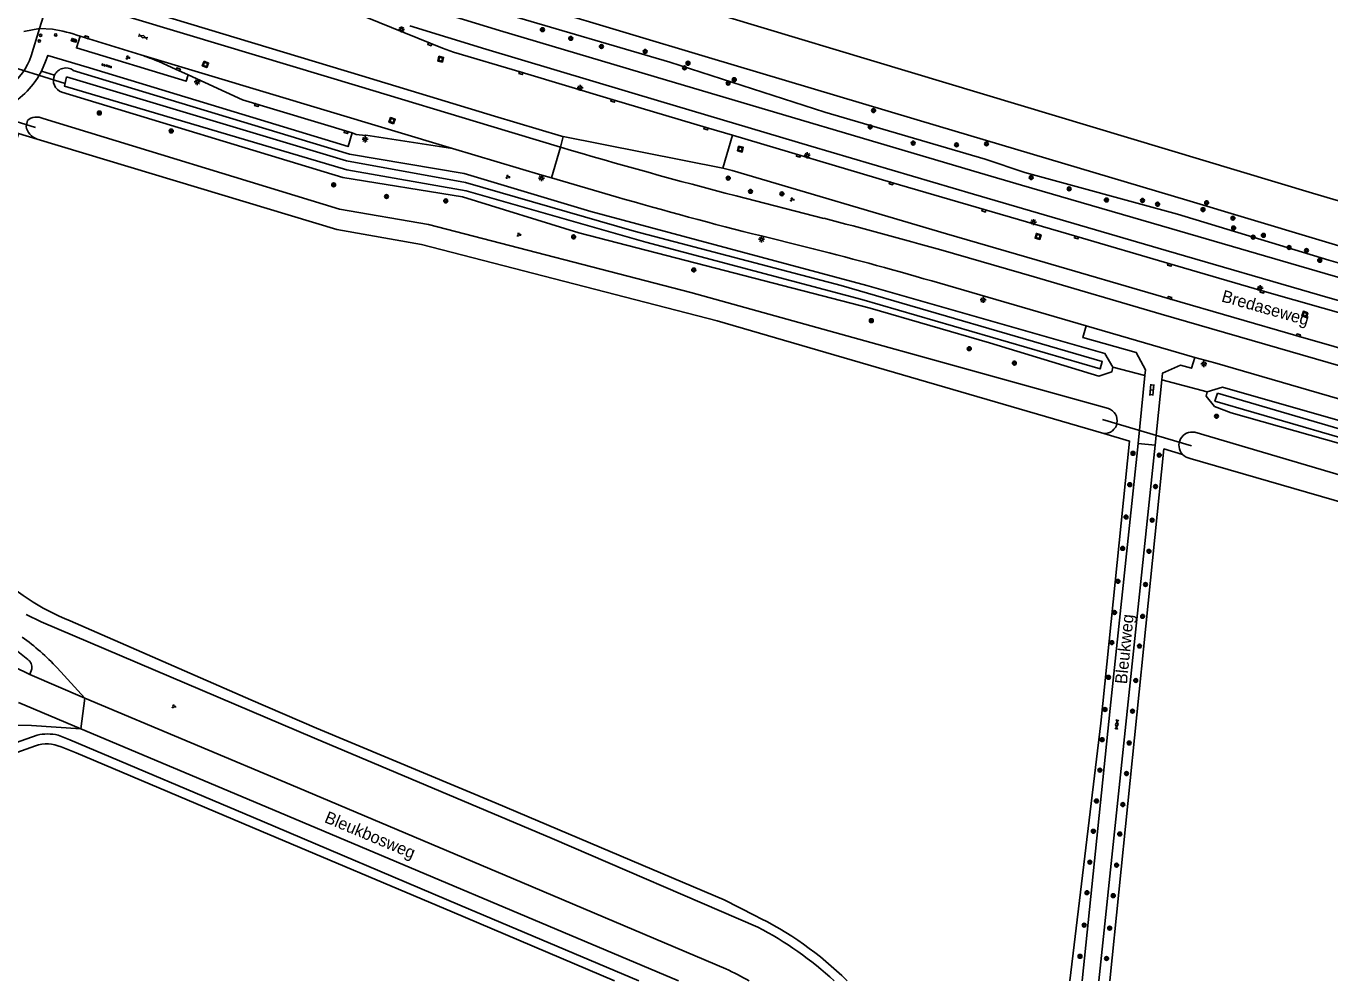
# Model space of a CAD drawing. Extents: x 125000 to 129004, y 397500 to 399008.
# Drawn here: x 126547.3 to 126817.1, y 397500 to 397697.5 of the extents above; entities that cross this region are included whole.
import ezdxf

# ---------------------------------------------------------------- set-up
doc = ezdxf.new("R2010")
doc.units = 0
for name, color, linetype in [('gg-afsc-draadraster', 7, 'Continuous'), ('gg-afsc-hekwerk', 7, 'Continuous'), ('gg-afsc-lijn draadraster', 7, 'Continuous'), ('gg-anno-openbare ruimte label', 7, 'Continuous'), ('gg-knt-bronhoudergrens', 7, 'Continuous'), ('gg-knt-verharding', 7, 'Continuous'), ('gg-knt-verharding nz', 7, 'Continuous'), ('gg-kntw-greppel-droge sloot', 7, 'Continuous'), ('gg-kntw-waterlijn', 7, 'Continuous'), ('gg-kwrk-duiker nz buis', 7, 'Continuous'), ('gt-grn-groengrens', 7, 'Continuous'), ('gt-grn-weggrens', 7, 'Continuous'), ('gt-symb-boom', 7, 'Continuous'), ('gt-symb-drukknoppaal', 7, 'Continuous'), ('gt-symb-gesloten verharding', 7, 'Continuous'), ('gt-symb-groenvak', 7, 'Continuous'), ('gt-symb-klinker verharding', 7, 'Continuous'), ('gt-symb-kolk', 7, 'Continuous'), ('gt-symb-lichtmast', 7, 'Continuous'), ('gt-symb-rioolschacht', 7, 'Continuous'), ('gt-symb-tegel verharding', 7, 'Continuous'), ('gt-symb-verkeersregelinstallatiekast', 7, 'Continuous'), ('gt-symb-verkeersregelinstallatiepaal', 7, 'Continuous'), ('gx-grn-maaiveld', 7, 'Continuous')]:
    doc.layers.add(name, color=color, linetype=linetype)

# ---------------------------------------------------------------- blocks, each defined once
blk = doc.blocks.new('gt0-BOOM')
at = {"layer": 'gt-symb-boom'}
for radius in [0.4, 0.2]:
    blk.add_circle((0, 0), radius, dxfattribs=at)
blk = doc.blocks.new('gt0-KOLK')
at = {"layer": 'gt-symb-kolk'}
blk.add_lwpolyline([(0, 0), (0.37, 0), (0.37, 0.4), (-0.38, 0.4), (-0.38, 0), (0, 0)], dxfattribs=at)
blk = doc.blocks.new('gt0-RS')
at = {"layer": 'gt-symb-rioolschacht'}
blk.add_lwpolyline([(-0.5, -0.5), (0.5, -0.5), (0.5, 0.5), (-0.5, 0.5)], close=True, dxfattribs=at)
blk.add_circle((0, 0), 0.375, dxfattribs=at)
blk = doc.blocks.new('gt0-LMAST')
at = {"layer": 'gt-symb-lichtmast'}
for p, q in [((-0.18, 0.17), (-0.45, 0.44)), ((-0.01, 0.25), (-0.01, 0.62)), ((0.17, 0.17), (0.44, 0.44)), ((-0.26, 0), (-0.63, 0)), ((-0.18, -0.18), (-0.45, -0.45)), ((-0.01, -0.25), (-0.01, -0.63)), ((0.44, -0.45), (0.17, -0.18)), ((0.24, 0), (0.62, 0))]:
    blk.add_line(p, q, dxfattribs=at)
blk.add_circle((-0.01, 0), 0.25, dxfattribs=at)
blk = doc.blocks.new('gt0-KL1')
at = {"layer": 'gt-symb-klinker verharding'}
for p, q in [((-1.15, 0.3), (1.15, 0.3)), ((-1, -0.3), (-1, 0.3)), ((-0.5, 0.3), (-0.5, 0.45)), ((0, -0.3), (0, 0.3)), ((0.5, 0.3), (0.5, 0.45)), ((1, -0.3), (1, 0.3)), ((-1.15, -0.3), (1.15, -0.3)), ((-0.5, -0.45), (-0.5, -0.3)), ((0.5, -0.45), (0.5, -0.3))]:
    blk.add_line(p, q, dxfattribs=at)
blk = doc.blocks.new('gt0-GESVH1')
at = {"layer": 'gt-symb-gesloten verharding'}
for p, q in [((-0.99, -0.26), (0.01, 0.24)), ((0.01, -0.26), (-0.99, 0.24)), ((0.01, 0.24), (1.01, -0.26)), ((1.01, 0.24), (0.01, -0.26))]:
    blk.add_line(p, q, dxfattribs=at)
blk = doc.blocks.new('gt0-GRVAK')
at = {"layer": 'gt-symb-groenvak'}
for p, q in [((-0.11, 0.19), (-0.23, 0.24)), ((-0.18, 0.15), (0.09, 0.15)), ((-0.09, 0.21), (-0.16, 0.32)), ((-0.05, 0.21), (-0.05, 0.39)), ((0, 0.21), (0.06, 0.32)), ((0.01, 0.19), (0.13, 0.24)), ((0.26, -0.05), (0.2, 0.06)), ((0.3, -0.05), (0.3, 0.13)), ((0.35, -0.05), (0.41, 0.06)), ((-0.24, -0.23), (-0.36, -0.18)), ((-0.32, -0.26), (-0.05, -0.26)), ((-0.23, -0.21), (-0.29, -0.09)), ((-0.18, -0.2), (-0.18, -0.02)), ((-0.14, -0.21), (-0.07, -0.09)), ((-0.12, -0.23), (0, -0.18)), ((0.24, -0.07), (0.12, -0.02)), ((0.17, -0.11), (0.44, -0.11)), ((0.37, -0.07), (0.49, -0.02))]:
    blk.add_line(p, q, dxfattribs=at)
blk = doc.blocks.new('gt0-TEG1')
at = {"layer": 'gt-symb-tegel verharding'}
for p, q in [((-1.12, 0), (1.12, 0)), ((-0.9, -0.25), (-0.9, 0.25)), ((-0.45, -0.25), (-0.45, 0.25)), ((0, -0.25), (0, 0.25)), ((0.45, -0.25), (0.45, 0.25)), ((0.9, -0.25), (0.9, 0.25))]:
    blk.add_line(p, q, dxfattribs=at)
blk = doc.blocks.new('gt0-DPAAL')
at = {"layer": 'gt-symb-drukknoppaal'}
blk.add_circle((0, 0), 0.25, dxfattribs=at)
blk = doc.blocks.new('gt0-VIPAAL')
at = {"layer": 'gt-symb-verkeersregelinstallatiepaal'}
blk.add_circle((0, 0), 0.25, dxfattribs=at)
blk = doc.blocks.new('gt0-VRIKST')
at = {"layer": 'gt-symb-verkeersregelinstallatiekast'}
for p, q in [((-0.5, -0.25), (0.5, 0.25)), ((-0.5, 0.25), (0.5, -0.25))]:
    blk.add_line(p, q, dxfattribs=at)
blk.add_lwpolyline([(0.5, 0.25), (-0.5, 0.25), (-0.5, -0.25), (0.5, -0.25)], close=True, dxfattribs=at)

msp = doc.modelspace()

# ---------------------------------------------------------------- linework, layer by layer
at = {"layer": 'gg-afsc-draadraster'}
msp.add_lwpolyline([(126680.86, 397850.53), (126672.24, 397845.08), (126589.63, 397738.35), (126608.57, 397724.72), (126813.52, 397663.01), (126844.57, 397653.81), (126855.71, 397650.92), (126946.81, 397622.37)], dxfattribs=at)
at = {"layer": 'gg-afsc-hekwerk'}
msp.add_lwpolyline([(126942.42, 397614.98), (126787.49, 397661.55), (126736.33, 397676.77), (126688.51, 397691.05), (126603.35, 397716.66)], dxfattribs=at)
msp.add_lwpolyline([(126942.42, 397614.98), (126787.49, 397661.55), (126736.33, 397676.77), (126688.51, 397691.05), (126603.35, 397716.66)], dxfattribs=at)
at = {"layer": 'gg-afsc-lijn draadraster'}
msp.add_lwpolyline([(126680.86, 397850.53), (126672.24, 397845.08), (126589.63, 397738.35), (126608.57, 397724.72), (126813.52, 397663.01), (126844.57, 397653.81), (126855.71, 397650.92), (126946.81, 397622.37)], dxfattribs=at)
at = {"layer": 'gg-knt-bronhoudergrens'}
for points in [[(126770.33, 397613.24), (126775.63, 397611.69), (126769.68, 397553.36), (126763.27, 397500)], [(126771.58, 397500), (126782.74, 397610.06), (126786.6, 397608.92)]]:
    msp.add_lwpolyline(points, dxfattribs=at)
at = {"layer": 'gg-knt-verharding'}
for p, q in [((126550.12, 397697.05), (126548.39, 397691.37)), ((126552.77, 397696.88), (126550.12, 397697.05)), ((126558.48, 397695.44), (126571.04, 397691.59)), ((126548.76, 397685.53), (126549.34, 397686.32)), ((126657.88, 397672.5), (126658.45, 397674.67)), ((126691.46, 397668.17), (126658.45, 397674.67)), ((126656.03, 397666.13), (126669.42, 397662.24)), ((126694.23, 397662.4), (126712.39, 397657.77)), ((126699.49, 397654.13), (126708.53, 397651.9)), ((126734.74, 397644.82), (126766.63, 397635.54)), ((126789.12, 397629.01), (126766.63, 397635.54)), ((126778.8, 397625.25), (126777.44, 397611.22)), ((126780.96, 397610.84), (126782.32, 397624.33)), ((126769.26, 397500), (126780.96, 397610.84)), ((126777.44, 397611.22), (126780.96, 397610.84)), ((126544.88, 397564.97), (126548.12, 397563.37)), ((126548.12, 397563.37), (126548.48, 397564.54)), ((126559.45, 397558.5), (126553.73, 397564.75)), ((126558.64, 397552.15), (126596.99, 397536.04)), ((126596.99, 397536.04), (126682.31, 397500))]:
    msp.add_line(p, q, dxfattribs=at)
for points in [[(126693.46, 397674.95), (126688.05, 397676.56), (126668.8, 397682.27), (126649.75, 397688.02), (126635.77, 397692.15), (126633.47, 397693), (126630.93, 397693.98), (126612.38, 397701.55), (126602.9, 397705.38), (126600.29, 397706.25), (126593.1, 397708.42), (126576.92, 397713.35), (126561.25, 397718.17), (126560.98, 397718.24)], [(126556, 397705.65), (126581.4, 397697.91), (126616.79, 397687.26), (126644.23, 397678.88), (126658.09, 397674.74), (126658.45, 397674.67)], [(126555.31, 397703.49), (126580.59, 397695.82), (126616.12, 397685.12), (126643.45, 397676.83), (126657.88, 397672.5)], [(126898.05, 397622.91), (126846.72, 397637.56), (126816.13, 397646.34), (126784.36, 397655.62), (126753.25, 397664.65), (126744.62, 397667.19), (126679.83, 397686.37), (126645.26, 397696.66), (126630.36, 397701.2)], [(126958.64, 397601.65), (126955.76, 397602.08), (126952.55, 397602.68), (126946.55, 397604.46), (126929.88, 397609.18), (126896.65, 397618.5), (126870.61, 397625.99), (126845.69, 397633.05), (126815.03, 397641.9), (126783.19, 397651.1), (126743.33, 397662.77), (126709.67, 397672.73), (126678.64, 397681.95), (126642.42, 397692.79), (126626.7, 397697.63)], [(126558.48, 397695.44), (126557.73, 397693.02), (126580.46, 397686.14), (126580.88, 397687.43)], [(126614.78, 397675.43), (126613.93, 397672.63), (126560.41, 397688.91), (126551.82, 397691.49), (126551.36, 397690.19)], [(126574.8, 397690.21), (126578.26, 397688.65), (126580.88, 397687.43)], [(126580.88, 397687.43), (126592.07, 397682.3), (126614.78, 397675.43)], [(126614.78, 397675.43), (126615.62, 397675.15), (126617.56, 397674.89), (126617.6, 397674.99), (126635.57, 397672.25)], [(127217.52, 397528.12), (127216.66, 397528.36), (127174.98, 397539.4), (127133.48, 397550.52), (127112.67, 397556.13), (127072.64, 397567.02), (127034.07, 397577.58), (126995.54, 397588.26), (126956.98, 397599.02), (126937.75, 397604.4), (126917.42, 397610.12), (126899.33, 397615.25), (126880, 397620.69), (126860.79, 397626.22), (126841.44, 397631.74), (126822.25, 397637.29), (126803.1, 397642.8), (126783.96, 397648.35), (126764.71, 397653.99), (126745.56, 397659.57), (126726.38, 397665.2), (126693.46, 397674.95)], [(126635.57, 397672.25), (126654, 397666.72), (126656.03, 397666.13)], [(127229.02, 397517.84), (127201.79, 397525.03), (127175.21, 397532.08), (127124.03, 397545.78), (127099.13, 397552.5), (127072.79, 397559.71), (127046.84, 397566.77), (126995.54, 397580.92), (126968.7, 397588.42), (126944.12, 397595.31), (126902.34, 397607.09), (126846.79, 397622.95), (126810.53, 397633.38), (126783.9, 397641.11), (126756.49, 397649.1), (126737.73, 397654.58), (126693.39, 397667.65), (126691.46, 397668.17)], [(127228.13, 397514.43), (127201.09, 397521.57), (127174.12, 397528.76), (127147.75, 397535.83), (127123.09, 397542.48), (127098.21, 397549.13), (127071.78, 397556.36), (127045.92, 397563.39), (126994.69, 397577.57), (126943.18, 397591.97), (126900.68, 397603.95), (126873.36, 397611.7), (126840.83, 397621.01), (126782.2, 397637.97), (126755.87, 397645.68), (126736.59, 397651.23)], [(126766.63, 397635.54), (126765.97, 397633.09), (126777.01, 397630.01), (126778.92, 397626.46), (126778.8, 397625.25)], [(126782.32, 397624.33), (126782.47, 397625.76), (126786.15, 397627.41), (126788.46, 397626.76), (126789.12, 397629.01)], [(127226.37, 397507.68), (127213.45, 397511.07), (127212.8, 397511.23), (127212.87, 397511.61), (127203.25, 397514.16), (127179.75, 397520.34), (127157.76, 397526.2), (127111.36, 397538.68), (127090.71, 397544.26), (127065.54, 397551.12), (127043.84, 397557.07), (127020.85, 397563.46), (126998.29, 397569.62), (126967.67, 397578.26), (126942.81, 397585.13), (126939.99, 397585.87), (126928.21, 397589.18), (126906.39, 397595.25), (126882.62, 397602.07), (126860.21, 397608.45), (126793.27, 397627.87), (126789.12, 397629.01)], [(126765.85, 397500), (126771.65, 397556.38), (126777.44, 397611.22)], [(126547.69, 397566.5), (126545.27, 397568.41), (126540.55, 397571.7)], [(126692.11, 397502.47), (126649.94, 397520.39), (126603.49, 397540.04), (126559.45, 397558.5)], [(126544.19, 397552.88), (126548.47, 397552.84), (126558.64, 397552.15)]]:
    msp.add_lwpolyline(points, dxfattribs=at)
for centre, radius, start, end in [((126549.02, 397670), 27.14, 69.5919, 82.0525), ((126534.84, 397696.3), 14.42, 308.6514, 340.0221), ((126557.21, 397648.26), 45.48, 67.2447, 72.2957), ((126534.6, 397696.43), 17.88, 305.9376, 322.4178), ((126968.34, 398720.06), 1092.6, 253.49189, 255.47078), ((126885.01, 398401.51), 770.07, 253.74218, 256.05935), ((126484.84, 396767.97), 918.44, 74.09133, 75.65505), ((126530.89, 396942.35), 731.44, 73.81825, 75.94442), ((126520.92, 397534.82), 44.41, 42.3806, 54.8381), ((126546.64, 397564.94), 1.88, 347.598, 56.2456), ((126669.46, 397452.63), 54.75, 59.9139, 65.5588)]:
    msp.add_arc(centre, radius, start, end, dxfattribs=at)
at = {"layer": 'gg-knt-verharding nz'}
for p, q in [((126552.36, 397704.36), (126550.12, 397697.05)), ((126550.12, 397697.05), (126546.84, 397696.42)), ((126571.04, 397691.59), (126635.57, 397672.25)), ((126657.88, 397672.5), (126656.03, 397666.13)), ((126691.46, 397668.17), (126693.46, 397674.95)), ((126548.12, 397563.37), (126559.45, 397558.5)), ((126558.64, 397552.15), (126545.74, 397557.58))]:
    msp.add_line(p, q, dxfattribs=at)
at = {"layer": 'gg-kntw-greppel-droge sloot'}
for p, q in [((126547.32, 397676.8), (126547.58, 397678.01)), ((126547.32, 397676.8), (126547.58, 397678.01)), ((126789.14, 397613.5), (126867.11, 397590.56)), ((126864.12, 397586.03), (126788.2, 397608.08)), ((126717.14, 397500.07), (126717.2, 397500))]:
    msp.add_line(p, q, dxfattribs=at)
for points in [[(126938.38, 397612.66), (126919.74, 397618.29), (126894.23, 397626.51), (126874.77, 397632.03), (126847.78, 397640.26), (126816.86, 397649.13), (126785.57, 397658.6), (126753.96, 397667.27), (126745.79, 397670), (126712.61, 397679.71), (126680.54, 397690.07), (126646.67, 397699.99), (126630.26, 397705.04), (126604.63, 397714.07), (126588.73, 397725.07), (126576.4, 397735.35), (126577.59, 397737.11)], [(126772.21, 397626.98), (126770.54, 397629.81), (126721.3, 397643.88), (126664.14, 397659.17), (126637.93, 397667.05), (126614.27, 397671.08), (126557.05, 397688.39)], [(126554.7, 397683.88), (126612.88, 397666.2), (126637.59, 397662.2), (126661.71, 397654.8), (126721.96, 397639.21), (126746.67, 397632), (126769.25, 397625.09), (126771.94, 397626.01), (126772.21, 397626.98)], [(126771.29, 397618.41), (126684.88, 397642.42), (126630.57, 397656.48), (126612.19, 397659.7), (126550.84, 397678.42)], [(126771.29, 397618.41), (126684.88, 397642.42), (126630.57, 397656.48), (126612.19, 397659.7), (126550.84, 397678.42)], [(126770.33, 397613.24), (126690.28, 397636.59), (126629.11, 397652.39), (126611.62, 397655.49), (126549.6, 397674.17)], [(126770.33, 397613.24), (126690.28, 397636.59), (126629.11, 397652.39), (126611.62, 397655.49), (126549.6, 397674.17)], [(126796.66, 397617.51), (126793.22, 397618.81), (126791.48, 397621), (126791.71, 397621.87)], [(126791.71, 397621.87), (126794.89, 397622.82), (126870.78, 397601.15), (126914.48, 397588.79), (126958.33, 397576.51), (126959.95, 397575.77), (126961.59, 397573.52)], [(126961.59, 397573.52), (126961.42, 397572.83), (126958.13, 397571.91), (126919.94, 397582.63), (126868.86, 397597.15), (126796.66, 397617.51)], [(126698.7, 397511.14), (126656.17, 397529.46), (126607.01, 397550.23), (126550.43, 397574.26), (126547.32, 397575.83)], [(126698.11, 397513.52), (126691.75, 397516.8), (126644.56, 397536.77), (126607.39, 397552.32), (126593.82, 397558.12), (126556.41, 397574.49)], [(126507.55, 397500), (126526.89, 397536.86), (126537.5, 397546.58), (126549.6, 397550.87)], [(126509.43, 397500), (126528.29, 397535.76), (126538.37, 397544.78), (126549.25, 397548.62)], [(126553.94, 397550.86), (126556.35, 397549.89), (126596.2, 397533.06), (126637.09, 397515.64), (126674.1, 397500)], [(126554.56, 397548.42), (126557.69, 397547.21), (126595.95, 397530.95), (126635.47, 397514.31), (126669.04, 397500)]]:
    msp.add_lwpolyline(points, dxfattribs=at)
for centre, radius, start, end in [((126555.55, 397686.31), 2.57, 54.2291, 154.6382), ((126549.55, 397675.57), 3.14, 65.5367, 128.8126), ((126549.55, 397675.57), 3.14, 65.5367, 128.8126), ((126550.75, 397677.48), 3.5, 191.1604, 250.7995), ((126550.75, 397677.48), 3.5, 191.1604, 250.7995), ((126770.42, 397615.89), 2.66, 267.9446, 71.0264), ((126770.42, 397615.89), 2.66, 267.9446, 71.0264), ((126788.61, 397610.8), 2.75, 78.9293, 222.9551), ((126788.62, 397610.8), 2.75, 222.9647, 261.3264), ((126573.25, 397617.23), 45.93, 199.8408, 248.4933), ((126551.76, 397540.65), 10.44, 77.9511, 101.9433), ((126551.65, 397541.94), 7.09, 65.805, 109.7475), ((126667.66, 397450.26), 70.21, 45.1917, 64.301), ((126663.67, 397444.51), 75.28, 47.4926, 62.2668)]:
    msp.add_arc(centre, radius, start, end, dxfattribs=at)
at = {"layer": 'gg-kntw-waterlijn'}
for points in [[(126555.68, 397687.05), (126613.62, 397669.68), (126638.25, 397665.22), (126673.15, 397655.1), (126715.98, 397643.87), (126769.98, 397628.14), (126769.54, 397626.62), (126720.25, 397640.98), (126675.55, 397652.87), (126638.35, 397663.45), (126613.67, 397667.79), (126555.25, 397685.12), (126555.68, 397687.05)], [(126793.84, 397621.57), (126824.69, 397612.59), (126958.99, 397574.91), (126958.53, 397573.28), (126825.56, 397610.59), (126793.3, 397619.97), (126793.84, 397621.57)]]:
    msp.add_lwpolyline(points, dxfattribs=at)
at = {"layer": 'gg-kwrk-duiker nz buis'}
for p, q in [((126555.43, 397685.66), (126513.51, 397698.62)), ((126514.7, 397687.16), (126549.28, 397676.59)), ((126788.45, 397610.71), (126770.04, 397616.14))]:
    msp.add_line(p, q, dxfattribs=at)
at = {"layer": 'gt-grn-groengrens'}
for p, q in [((126553.22, 397687.41), (126550.49, 397688.24)), ((126778.8, 397625.25), (126772.21, 397626.98)), ((126791.71, 397621.87), (126782.32, 397624.33))]:
    msp.add_line(p, q, dxfattribs=at)
at = {"layer": 'gt-grn-weggrens'}
msp.add_line((126558.64, 397552.15), (126559.45, 397558.5), dxfattribs=at)
at = {"layer": 'gx-grn-maaiveld'}
msp.add_line((126550.49, 397688.24), (126551.36, 397690.19), dxfattribs=at)
msp.add_lwpolyline([(126549.6, 397674.17), (126545.72, 397675.34), (126531.44, 397627.54), (126529.31, 397618.27), (126528.84, 397616.01)], dxfattribs=at)
for centre, radius, start, end in [((126535.79, 397695.73), 16.5, 325.2249, 332.9883), ((126555.55, 397686.31), 2.57, 154.603, 250.7082)]:
    msp.add_arc(centre, radius, start, end, dxfattribs=at)

# ---------------------------------------------------------------- block references
at = {"layer": 'gt-symb-boom'}
for p in [(126654.15, 397696.81), (126660.02, 397695), (126666.36, 397693.33), (126675.42, 397692.31), (126683.56, 397688.9), (126684.27, 397689.86), (126692.59, 397685.74), (126693.84, 397686.46), (126562.48, 397679.56), (126722.67, 397680.07), (126577.35, 397675.84), (126721.96, 397676.69), (126730.86, 397673.34), (126739.84, 397672.97), (126746.03, 397673.18), (126610.96, 397664.71), (126692.6, 397666.08), (126755.28, 397666.2), (126621.9, 397662.28), (126634.15, 397661.38), (126697.2, 397663.35), (126703.71, 397662.85), (126763.14, 397663.87), (126770.85, 397661.56), (126778.32, 397661.48), (126781.44, 397660.69), (126790.83, 397659.58), (126791.58, 397660.99), (126797.03, 397657.81), (126660.61, 397653.93), (126797.17, 397655.77), (126801.21, 397653.87), (126803.33, 397654.26), (126808.64, 397651.73), (126812.24, 397651.11), (126814.99, 397649.08), (126685.47, 397647.09), (126722.21, 397636.6), (126742.47, 397630.8), (126751.81, 397627.82), (126793.63, 397616.82), (126776.35, 397609.15), (126781.79, 397608.78), (126775.68, 397602.67), (126781.01, 397602.28), (126774.91, 397595.97), (126780.32, 397595.33), (126774.21, 397589.49), (126779.65, 397588.89), (126773.24, 397582.68), (126778.94, 397582.01), (126772.54, 397576.23), (126778.34, 397575.42), (126771.98, 397569.99), (126777.69, 397569.28), (126771.27, 397562.81), (126776.91, 397562.16), (126770.56, 397556.15), (126776.25, 397555.8), (126769.96, 397549.91), (126775.56, 397549.22), (126769.5, 397543.61), (126775, 397542.9), (126768.78, 397537.22), (126774.24, 397536.48), (126768.15, 397530.96), (126773.61, 397530.4), (126767.41, 397524.56), (126772.96, 397523.95), (126766.82, 397518.25), (126772.26, 397517.64), (126766.25, 397511.53), (126771.52, 397510.92), (126765.38, 397505.08), (126770.88, 397504.64)]:
    msp.add_blockref('gt0-BOOM', p, dxfattribs=at)
at = {"layer": 'gt-symb-drukknoppaal'}
msp.add_blockref('gt0-DPAAL', (126550.04, 397694.45), dxfattribs=at)
at = {"layer": 'gt-symb-gesloten verharding'}
for p, rotation in [((126571.5, 397695.36), -21.280166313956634), ((126773.01, 397553.07), -95.39146339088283)]:
    msp.add_blockref('gt0-GESVH1', p, dxfattribs=dict(at, rotation=rotation))
at = {"layer": 'gt-symb-groenvak'}
for p in [(126568.34, 397691.05), (126646.96, 397666.36), (126705.79, 397661.68), (126649.25, 397654.41), (126577.86, 397556.81)]:
    msp.add_blockref('gt0-GRVAK', p, dxfattribs=at)
at = {"layer": 'gt-symb-klinker verharding', "rotation": -94.99208116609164}
msp.add_blockref('gt0-KL1', (126780.26, 397622.27), dxfattribs=at)
at = {"layer": 'gt-symb-kolk'}
for p, rotation in [((126559.79, 397695.04), -17.179268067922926), ((126630.93, 397693.98), 157.7805118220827), ((126578.75, 397688.42), -24.64832408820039), ((126649.75, 397688.02), 163.5303117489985), ((126595.08, 397681.39), 163.06577358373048), ((126668.8, 397682.27), 163.21882741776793), ((126613.57, 397675.79), 163.16781198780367), ((126688.05, 397676.56), 163.4615356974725), ((126707.17, 397670.9), 163.51254628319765), ((126726.38, 397665.2), 163.48704137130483), ((126745.56, 397659.57), 163.63778587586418), ((126764.71, 397653.99), 163.67330293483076), ((126783.96, 397648.35), 163.84179091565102), ((126803.1, 397642.8), 163.94154016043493), ((126783.9, 397641.11), -16.242452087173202), ((126810.53, 397633.38), -16.183706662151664)]:
    msp.add_blockref('gt0-KOLK', p, dxfattribs=dict(at, rotation=rotation))
at = {"layer": 'gt-symb-lichtmast'}
for p in [(126625, 397696.87), (126582.74, 397685.98), (126661.96, 397684.76), (126617.47, 397674.12), (126708.95, 397670.81), (126653.96, 397666.1), (126755.74, 397657.01), (126699.5, 397653.43), (126802.66, 397643.32), (126745.34, 397640.9), (126791.04, 397627.64)]:
    msp.add_blockref('gt0-LMAST', p, dxfattribs=at)
at = {"layer": 'gt-symb-rioolschacht'}
for p, rotation in [((126633.1, 397690.69), -13.636976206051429), ((126584.43, 397689.62), -111.7519545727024), ((126623.05, 397677.99), 69.80662329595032), ((126695.11, 397672.09), -12.932317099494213), ((126756.71, 397654.03), 164.75408248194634), ((126811.93, 397637.91), 163.15002656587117)]:
    msp.add_blockref('gt0-RS', p, dxfattribs=dict(at, rotation=rotation))
at = {"layer": 'gt-symb-tegel verharding', "rotation": -14.95356475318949}
msp.add_blockref('gt0-TEG1', (126564, 397689.33), dxfattribs=at)
at = {"layer": 'gt-symb-verkeersregelinstallatiekast', "rotation": -18.442604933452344}
msp.add_blockref('gt0-VRIKST', (126557.23, 397694.6), dxfattribs=at)
at = {"layer": 'gt-symb-verkeersregelinstallatiepaal'}
for p in [(126550.32, 397695.65), (126553.45, 397695.72)]:
    msp.add_blockref('gt0-VIPAAL', p, dxfattribs=at)

# ---------------------------------------------------------------- texts
at = {"layer": 'gg-anno-openbare ruimte label'}
for s, rotation, p in [('Bredaseweg', 344.2, (126794.5, 397640.6)), ('Bleukweg', 84.4, (126775.09, 397561.33)), ('Bleukbosweg', 337.2, (126608.87, 397532.9))]:
    msp.add_text(s, height=2.5, rotation=rotation, dxfattribs=at).set_placement(p)

doc.saveas('drawing.dxf')
